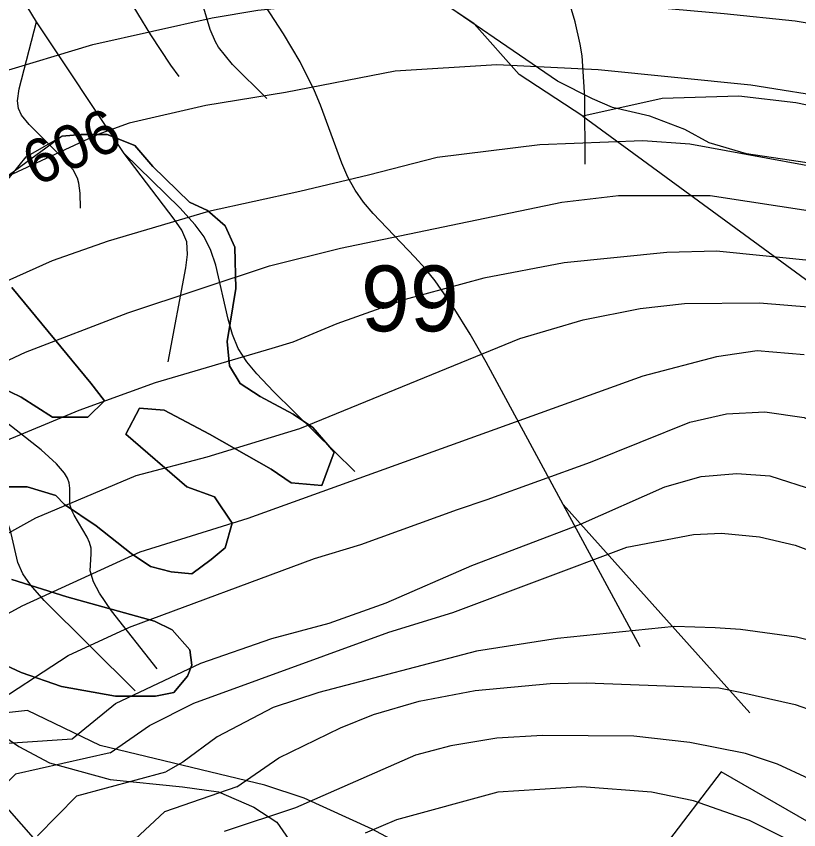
# Model space of a CAD drawing. Extents: x -709584 to -702006, y -1161789 to -1157496.
# Drawn here: x -707476.6 to -707298.4, y -1160186.2 to -1160000.8 of the extents above; entities that cross this region are included whole.
import ezdxf

# ---------------------------------------------------------------- set-up
doc = ezdxf.new("R2010")
doc.units = 0
for name, color, linetype in [('120_vrstevnice hlavní', 7, 'Continuous'), ('121_vrstevnice hlavní_popis', 7, 'Continuous'), ('122_vrstevnice základní', 7, 'Continuous'), ('408_BPEJ_linie', 7, 'Continuous'), ('409_BPEJ_popis', 7, 'Continuous'), ('411_akumulovaný odtok', 7, 'Continuous'), ('419_LPIS PB', 7, 'Continuous')]:
    doc.layers.add(name, color=color, linetype=linetype)

msp = doc.modelspace()

# ---------------------------------------------------------------- linework, layer by layer
at = {"layer": '120_vrstevnice hlavní'}
for points in [[(-707608.13, -1160158.91), (-707604.37, -1160160.5), (-707597.43, -1160159.92), (-707593.67, -1160158.04), (-707587.73, -1160153.12), (-707570.81, -1160135.91), (-707559.24, -1160126.07), (-707543.91, -1160114.65), (-707533.78, -1160108.28), (-707497.04, -1160087.89), (-707474.48, -1160077.33), (-707451.19, -1160068.36), (-707418.94, -1160057.66), (-707402.73, -1160053.61), (-707352.32, -1160043.09), (-707339.38, -1160041.6), (-707318.55, -1160041.6), (-707294.25, -1160045.36)], [(-707463.84, -1160165.44), (-707454.01, -1160157.37), (-707434.56, -1160148.21), (-707418.36, -1160142.56), (-707405.34, -1160139.09), (-707392.32, -1160134.46), (-707372.79, -1160125.93), (-707348.06, -1160116.53), (-707328.82, -1160107.99), (-707320.58, -1160105.68), (-707312.48, -1160104.96), (-707304.96, -1160105.53), (-707294.54, -1160108.86), (-707287.6, -1160112.62), (-707270.24, -1160124.77), (-707256.35, -1160131.72), (-707239, -1160141.99), (-707232.34, -1160147.19), (-707214.99, -1160165.13), (-707200.37, -1160178.58)], [(-707514.4, -1160190.44), (-707488.8, -1160167.15), (-707463.84, -1160165.44)], [(-707257.8, -1160229.06), (-707266.37, -1160218.79), (-707278.72, -1160204.35), (-707285.86, -1160198.11), (-707294.83, -1160191.45), (-707309.58, -1160184.08), (-707322.31, -1160179.59), (-707331.86, -1160177.57), (-707347.77, -1160176.41), (-707366.86, -1160177.57), (-707390.01, -1160183.93), (-707397.09, -1160186.97)]]:
    msp.add_lwpolyline(points, dxfattribs=at)
at = {"layer": '122_vrstevnice základní'}
for points in [[(-707552.16, -1160057.41), (-707538.7, -1160045.8), (-707519.46, -1160032.78), (-707507.31, -1160025.55), (-707497.33, -1160020.34), (-707480.84, -1160013.69), (-707459.15, -1160007.18), (-707431.95, -1160001.1), (-707421.54, -1159999.37), (-707405.92, -1159997.78), (-707379.3, -1159997.05), (-707330.7, -1159998.79), (-707315.37, -1160000.09), (-707299.17, -1160001.82), (-707286.73, -1160003.85)], [(-707289.33, -1160019.62), (-707309.29, -1160016.44), (-707344.01, -1160012.96), (-707367.15, -1160011.81), (-707390.3, -1160013.25), (-707415.25, -1160018.15), (-707433.4, -1160021.06), (-707450.9, -1160025.11), (-707457.99, -1160027.72), (-707490.39, -1160042.76), (-707507.75, -1160052.31), (-707518.16, -1160059.25), (-707536.39, -1160073.57), (-707548.39, -1160084.71)], [(-707280.08, -1160037.84), (-707323.18, -1160029.89), (-707333.88, -1160029.16), (-707357.32, -1160030.03), (-707380.75, -1160032.92), (-707396.37, -1160036.97), (-707411.99, -1160040.73), (-707432.82, -1160045.22), (-707455.67, -1160052.02), (-707468.4, -1160056.5), (-707496.61, -1160069.08), (-707510.93, -1160076.46), (-707522.5, -1160083.69), (-707544.34, -1160099.03), (-707567.2, -1160119.86), (-707577.75, -1160128.24), (-707585.28, -1160131.86), (-707593.38, -1160133.89), (-707598.01, -1160133.89)], [(-707178.54, -1160122.31), (-707224.08, -1160096.9), (-707236.78, -1160085.44), (-707252.02, -1160072.7), (-707263.59, -1160065.9), (-707276.32, -1160060.7), (-707293.67, -1160056.65), (-707317.1, -1160054.33), (-707328.39, -1160054.62), (-707351.82, -1160056.94), (-707370.05, -1160060.41), (-707387.98, -1160065.32), (-707403.6, -1160070.82), (-707413.58, -1160075.02), (-707418.36, -1160076.46), (-707444.97, -1160084.27), (-707462.33, -1160090.64), (-707480.84, -1160098.3), (-707489.52, -1160102.79), (-707500.8, -1160110.89), (-707517.87, -1160121.88), (-707543.18, -1160141.12)], [(-707522.51, -1160146.5), (-707506.89, -1160135.25), (-707496.46, -1160128.53), (-707472.16, -1160115.08), (-707449.31, -1160105.39), (-707433.11, -1160101.2), (-707411.99, -1160094.69), (-707361.89, -1160074.22), (-707347.48, -1160069.95), (-707334.46, -1160067.35), (-707324.34, -1160066.19), (-707307.27, -1160066.05), (-707289.77, -1160067.49), (-707228.15, -1160106.11)], [(-707297.14, -1160077.91), (-707307.85, -1160077.04), (-707317.1, -1160078.34), (-707333.89, -1160082.79), (-707423.85, -1160115.23), (-707448.44, -1160122.89), (-707475.35, -1160135.19), (-707494.15, -1160145.46), (-707499.94, -1160149.65), (-707503.4, -1160151.58)], [(-707483.93, -1160158.93), (-707464.79, -1160146.47), (-707450.76, -1160139.96), (-707408.67, -1160124.34), (-707398.11, -1160121.16), (-707376.12, -1160113.2), (-707369.32, -1160110.89), (-707345.75, -1160102.35), (-707323.18, -1160093.24), (-707314.79, -1160091.36), (-707306.11, -1160090.93), (-707297.14, -1160092.23), (-707287.31, -1160097), (-707265.61, -1160111.47), (-707245.36, -1160126.94), (-707225.69, -1160140.11), (-707215.85, -1160149.07), (-707192.85, -1160173.08), (-707171.93, -1160185.32)], [(-707455.2, -1160168.65), (-707446.27, -1160162.38), (-707436.15, -1160157.32), (-707391.74, -1160141.12), (-707377.13, -1160136.63), (-707337.5, -1160121.74), (-707322.31, -1160118.84), (-707315.95, -1160118.55), (-707307.27, -1160119.42), (-707299.17, -1160121.3), (-707291.07, -1160124.34), (-707282.1, -1160128.82), (-707266.19, -1160139.24), (-707259.1, -1160144.88), (-707256.5, -1160148.06), (-707224.3, -1160171.28)], [(-707211.9, -1160221.01), (-707224.39, -1160207.94), (-707230.17, -1160200.57), (-707236.97, -1160188.42), (-707244.35, -1160177.57), (-707251.44, -1160169.32), (-707263.01, -1160157.61), (-707271.11, -1160151.68), (-707278.05, -1160148.06), (-707284.13, -1160145.89), (-707298.88, -1160142.28), (-707311.61, -1160140.54), (-707317.39, -1160140.11), (-707326.65, -1160139.82), (-707353.27, -1160142.56), (-707371.78, -1160145.46), (-707407.65, -1160154.86), (-707418.07, -1160158.33), (-707430.8, -1160164.98), (-707438.61, -1160170.77), (-707442.51, -1160172.94)], [(-707426.38, -1160176.36), (-707416.8, -1160169.76), (-707402.73, -1160162.96), (-707395.21, -1160159.92), (-707384.8, -1160156.88), (-707372.07, -1160154.43), (-707355, -1160152.83), (-707346.76, -1160152.69), (-707316.53, -1160153.85), (-707311.32, -1160154.86), (-707299.17, -1160157.61), (-707290.49, -1160160.65), (-707278.34, -1160166.14), (-707271.4, -1160171.06), (-707262.72, -1160179.16), (-707248.98, -1160194.93), (-707244.48, -1160201.67), (-707238.18, -1160213.02)], [(-707237.26, -1160238.9), (-707249.98, -1160224.04), (-707257.04, -1160212.05), (-707263.44, -1160203.17), (-707276.03, -1160189.43), (-707284.99, -1160181.62), (-707295.99, -1160174.53), (-707303.22, -1160171.2), (-707310.45, -1160168.75), (-707323.18, -1160166.29), (-707335.91, -1160164.84), (-707356.74, -1160164.7), (-707367.15, -1160165.27), (-707377.57, -1160167.01), (-707385.67, -1160169.18), (-707413, -1160181.19)], [(-707455.2, -1160168.65), (-707476.79, -1160173.52), (-707485.47, -1160182.2), (-707509.19, -1160203.75)], [(-707471.73, -1160187.55), (-707462.76, -1160178.44), (-707442.51, -1160172.94)], [(-707426.38, -1160176.36), (-707442.85, -1160182.09), (-707491.84, -1160227.76)], [(-707413, -1160181.19), (-707429.2, -1160186.54)]]:
    msp.add_lwpolyline(points, dxfattribs=at)
at = {"layer": '408_BPEJ_linie'}
for points in [[(-707347.5, -1160023.5), (-707362, -1160014), (-707372.32, -1160002.51), (-707375.98, -1160000)], [(-707172, -1160103), (-707234.5, -1160051), (-707251, -1160038), (-707261, -1160034), (-707271.5, -1160028), (-707282, -1160024), (-707299, -1160020.5), (-707312, -1160019), (-707329.5, -1160019.5), (-707347.5, -1160023.5)], [(-707347.5, -1160023.5), (-707287.5, -1160067.5)], [(-707485.62, -1160108.01), (-707474.11, -1160108.01), (-707467.6, -1160110.01), (-707465.59, -1160112.02), (-707458.4, -1160116.9), (-707450.4, -1160123.2), (-707446, -1160126.2), (-707441.3, -1160127.4), (-707436.6, -1160127.8), (-707432.2, -1160124.6), (-707429, -1160121.9), (-707427.4, -1160116.3), (-707431.4, -1160110.3), (-707437.7, -1160108), (-707451.6, -1160096), (-707448.5, -1160090.1), (-707442.9, -1160090.5), (-707432.6, -1160096), (-707418.54, -1160103.99), (-707414, -1160107.1), (-707407, -1160107.7), (-707404.2, -1160100.1), (-707409.02, -1160094.46), (-707413.53, -1160091.45), (-707421.04, -1160087.43), (-707425.55, -1160084.42), (-707428.05, -1160080.41), (-707428.55, -1160074.89), (-707426.55, -1160062.84), (-707426.8, -1160053.4), (-707429, -1160048.5), (-707433, -1160045), (-707437.1, -1160043.1), (-707445.5, -1160035), (-707449.57, -1160030.22), (-707455.9, -1160027.7), (-707461.8, -1160027.7), (-707466.1, -1160028.1), (-707479.3, -1160037.7)], [(-707477.6, -1160062.6), (-707459.6, -1160084.4), (-707456.5, -1160088.4), (-707460.3, -1160092.1), (-707468.3, -1160092.1), (-707475.5, -1160087.6), (-707500, -1160075.73)], [(-707486.5, -1160145.2), (-707475.5, -1160150.3), (-707466.3, -1160153.5), (-707454, -1160155.7), (-707444.9, -1160155.7), (-707440.7, -1160154.9), (-707437.56, -1160151.17), (-707436.56, -1160148.66), (-707437.06, -1160145.15), (-707441.07, -1160140.63), (-707445.07, -1160138.62), (-707465.09, -1160133.1), (-707477.61, -1160129.09)], [(-707343.5, -1160214), (-707395.5, -1160186), (-707411, -1160179), (-707420, -1160176), (-707457.5, -1160167), (-707474, -1160159), (-707483, -1160160)], [(-707296, -1160184.5), (-707316, -1160173), (-707329, -1160190), (-707306.5, -1160201.5), (-707300, -1160206), (-707295, -1160215)]]:
    msp.add_lwpolyline(points, dxfattribs=at)
at = {"layer": '411_akumulovaný odtok'}
for p, q in [((-707451.99, -1160032), (-707471.99, -1160002)), ((-707334.49, -1160144.5), (-707351.99, -1160112)), ((-707309.49, -1160159.5), (-707351.99, -1160112))]:
    msp.add_line(p, q, dxfattribs=at)
for points in [[(-707439.49, -1160014.5), (-707441.38, -1160011.89), (-707445.93, -1160004.95), (-707451.84, -1159995.16), (-707454.89, -1159989.66), (-707457.76, -1159984), (-707464.91, -1159968.09), (-707467.05, -1159963.94), (-707469.41, -1159959.89), (-707479.46, -1159943.86), (-707481.8, -1159939.77), (-707483.94, -1159935.59), (-707485.91, -1159931.14), (-707491.25, -1159917.62), (-707493.22, -1159913.26), (-707495.48, -1159909.07), (-707498.28, -1159904.9), (-707501.42, -1159900.93), (-707515.22, -1159885.51), (-707533.14, -1159863.02), (-707536.55, -1159859.19), (-707543.72, -1159851.82), (-707562.55, -1159833.85)], [(-707471.99, -1160002), (-707478.95, -1159990.51), (-707484.2, -1159982.62), (-707487.01, -1159978.74), (-707492.33, -1159972.22), (-707504.24, -1159959.28), (-707510.87, -1159951.39), (-707514.63, -1159945.89), (-707519.1, -1159937.87), (-707520.95, -1159935.2), (-707523.02, -1159932.68), (-707525.28, -1159930.3), (-707527.7, -1159928.09), (-707530.27, -1159926.06), (-707532.99, -1159924.28), (-707541.31, -1159920.15), (-707547.27, -1159916.81), (-707553.09, -1159912.98), (-707561.53, -1159906.59), (-707566.83, -1159901.96), (-707572.06, -1159897.04), (-707596.99, -1159872)], [(-707346.99, -1160034.5), (-707347.06, -1160019.26), (-707347.71, -1160009.74), (-707348.11, -1160007.11), (-707349.31, -1160002.02), (-707353.02, -1159989.47), (-707354.24, -1159984.49), (-707354.9, -1159979.56), (-707354.87, -1159977.12), (-707354.52, -1159974.71), (-707353.9, -1159972.32), (-707352.16, -1159967.56), (-707350, -1159962.83), (-707342.91, -1159948.67), (-707339.81, -1159941.61), (-707339.02, -1159939.27), (-707338.44, -1159936.94), (-707338.16, -1159934.77), (-707338.15, -1159932.65), (-707338.49, -1159930.55), (-707339.36, -1159928.37), (-707340.75, -1159926.2), (-707350.98, -1159913.49), (-707351.99, -1159912)], [(-707419.49, -1160019.5), (-707427.3, -1160011.75), (-707430.5, -1160007.79), (-707431.22, -1160006.57), (-707432.45, -1160003.75), (-707435.99, -1159991.7), (-707437.12, -1159988.82), (-707437.81, -1159987.46), (-707440.41, -1159983.89), (-707448.53, -1159975.1), (-707450.21, -1159972.77), (-707450.87, -1159971.53), (-707451.71, -1159968.81), (-707452.1, -1159965.66), (-707452.19, -1159959.69), (-707451.99, -1159952)], [(-707351.99, -1160112), (-707369.54, -1160079.6), (-707373.23, -1160073.18), (-707377.06, -1160066.97), (-707381.2, -1160061.03), (-707383.45, -1160058.23), (-707385.77, -1160055.64), (-707395.32, -1160045.72), (-707397.48, -1160043.12), (-707399.4, -1160040.38), (-707401.05, -1160037.39), (-707402.46, -1160034.25), (-707407.29, -1160021.03), (-707408.63, -1160017.74), (-707411.93, -1160011.14), (-707415.73, -1160004.74), (-707419.79, -1159998.45), (-707426.12, -1159989.11), (-707451.99, -1159952)], [(-707461.99, -1160044.5), (-707462, -1160041.11), (-707462.31, -1160038.81), (-707462.62, -1160037.69), (-707463.6, -1160035.76), (-707466.11, -1160032.92), (-707473.66, -1160025.43), (-707475.36, -1160023.29), (-707476.1, -1160021.76), (-707476.29, -1160020.04), (-707475.95, -1160017.28), (-707471.99, -1160002)], [(-707468.35, -1160192.97), (-707486.34, -1160172.49), (-707489.77, -1160168.35), (-707493.01, -1160164.13), (-707495.98, -1160159.78), (-707498.59, -1160155.24), (-707500.58, -1160150.89), (-707502.27, -1160146.38), (-707503.77, -1160141.78), (-707507.93, -1160127.85), (-707509.46, -1160123.3), (-707514.26, -1160110.92), (-707518.65, -1160097.65), (-707520.32, -1160093.34), (-707522.43, -1160088.92), (-707524.82, -1160084.62), (-707532.29, -1160072.29), (-707534.82, -1160068.45), (-707538.54, -1160063.91), (-707543.24, -1160059.11), (-707548.59, -1160054.23), (-707559.94, -1160044.87), (-707576.99, -1160032)], [(-707441.99, -1160079.5), (-707437.97, -1160058.08), (-707437.6, -1160055.07), (-707437.77, -1160052.19), (-707438.91, -1160049.52), (-707440.59, -1160046.97), (-707451.99, -1160032)], [(-707399.49, -1160104.5), (-707418, -1160086.27), (-707421.8, -1160082.27), (-707424.1, -1160079.48), (-707426.02, -1160076.49), (-707427.36, -1160073.25), (-707428.33, -1160069.82), (-707431.14, -1160057.48), (-707432.24, -1160054.12), (-707433.79, -1160051.05), (-707435.81, -1160048.29), (-707439.32, -1160044.38), (-707451.99, -1160032)], [(-707449.49, -1160154.5), (-707470.22, -1160133.94), (-707473.36, -1160130.38), (-707475.1, -1160127.86), (-707476.24, -1160125.28), (-707477.73, -1160118.68), (-707478.59, -1160116.01), (-707480.53, -1160112.09), (-707484.93, -1160104.4), (-707486.06, -1160101.63), (-707486.46, -1160099.93), (-707486.92, -1160096.13), (-707487.06, -1160092.32), (-707486.99, -1160087)], [(-707444.49, -1160149.5), (-707454.93, -1160136.27), (-707457.65, -1160132.28), (-707459.02, -1160129.68), (-707459.72, -1160127.13), (-707459.49, -1160123.25), (-707459.55, -1160121.99), (-707459.89, -1160120.72), (-707460.45, -1160119.47), (-707463.43, -1160114.47), (-707464, -1160113.22), (-707464.36, -1160111.99), (-707464.36, -1160108.32), (-707464.5, -1160107.13), (-707464.91, -1160106.02), (-707465.58, -1160104.93), (-707467.43, -1160102.78), (-707470.95, -1160099.6), (-707486.99, -1160087)]]:
    msp.add_lwpolyline(points, dxfattribs=at)
at = {"layer": '419_LPIS PB'}
for points in [[(-707286.72, -1160035.61), (-707310.25, -1160032.1), (-707318.76, -1160029.59), (-707324.27, -1160026.57), (-707332.28, -1160023.56), (-707340.79, -1160021.55), (-707345.3, -1160019.54), (-707353.31, -1160015.52), (-707384.84, -1159993.93)], [(-707479.12, -1160038.69), (-707474.36, -1160032.76), (-707466.1, -1160028.1), (-707461.8, -1160027.7), (-707455.9, -1160027.7), (-707449.57, -1160030.22), (-707445.5, -1160035), (-707437.1, -1160043.1), (-707433, -1160045), (-707429, -1160048.5), (-707426.8, -1160053.4), (-707426.55, -1160062.84), (-707428.55, -1160074.89), (-707428.05, -1160080.41), (-707425.55, -1160084.42), (-707421.04, -1160087.43), (-707413.53, -1160091.45), (-707409.02, -1160094.46), (-707404.2, -1160100.1), (-707407, -1160107.7), (-707414, -1160107.1), (-707418.54, -1160103.99), (-707432.6, -1160096), (-707442.9, -1160090.5), (-707448.5, -1160090.1), (-707451.6, -1160096), (-707437.7, -1160108), (-707431.4, -1160110.3), (-707427.4, -1160116.3), (-707429, -1160121.9), (-707432.2, -1160124.6), (-707436.6, -1160127.8), (-707441.3, -1160127.4), (-707446, -1160126.2), (-707450.4, -1160123.2), (-707458.4, -1160116.9), (-707465.59, -1160112.02), (-707467.6, -1160110.01), (-707474.11, -1160108.01), (-707485.62, -1160108.01)], [(-707504.8, -1160073.4), (-707475.5, -1160087.6), (-707468.3, -1160092.1), (-707460.3, -1160092.1), (-707456.5, -1160088.4), (-707459.6, -1160084.4), (-707477.6, -1160062.6)], [(-707477.61, -1160129.09), (-707465.09, -1160133.1), (-707445.07, -1160138.62), (-707441.07, -1160140.63), (-707437.06, -1160145.15), (-707436.56, -1160148.66), (-707437.56, -1160151.17), (-707440.7, -1160154.9), (-707444.9, -1160155.7), (-707454, -1160155.7), (-707466.3, -1160153.5), (-707475.5, -1160150.3), (-707486.5, -1160145.2)], [(-707483, -1160162.4), (-707476, -1160167.2), (-707469.04, -1160170.89), (-707455.2, -1160174.7), (-707438.7, -1160176.4), (-707430.5, -1160177.5), (-707422.5, -1160181), (-707417.2, -1160184.4), (-707413.1, -1160190.4)]]:
    msp.add_lwpolyline(points, dxfattribs=at)

# ---------------------------------------------------------------- texts
at = {"layer": '121_vrstevnice hlavní_popis'}
msp.add_text('606', height=10, rotation=24.5487, dxfattribs=at).set_placement((-707472.14, -1160039.65))
at = {"layer": '409_BPEJ_popis'}
msp.add_text('99', height=15, dxfattribs=at).set_placement((-707398.08, -1160072.57))

doc.saveas('drawing.dxf')
